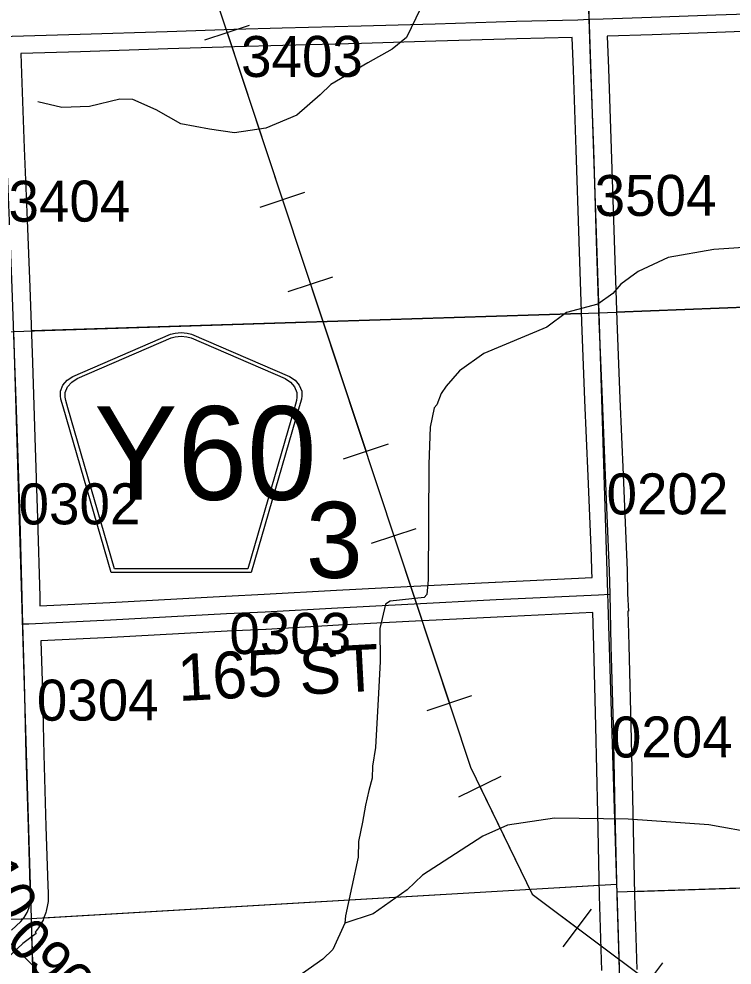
# Model space of a CAD drawing. Extents: x 128.7 to 185.5, y -21.4 to 12.6.
# Drawn here: x 149.009 to 150.229, y -2.33 to -0.713 of the extents above; entities that cross this region are included whole.
import ezdxf

# ---------------------------------------------------------------- set-up
doc = ezdxf.new("R2010")
doc.units = 0
for name, color, linetype in [('tdCoHydroRiver', 7, 'Continuous'), ('tdCoPipe', 7, 'Continuous'), ('tdCoPriDiv', 7, 'Continuous'), ('tdCoSecRdNmbr', 7, 'Continuous'), ('tdCoSecRdTxt', 7, 'Continuous'), ('tdCoSecRteBand', 7, 'Continuous'), ('tdCoSecRteCL', 7, 'Continuous'), ('tdCoSectLine', 7, 'Continuous'), ('tdCoSectLinePart', 7, 'Continuous'), ('tdCoSectNmbr', 7, 'Continuous'), ('tdCoShieldCoRteHrd', 7, 'Continuous'), ('tdCoSurfAsphalt', 7, 'Continuous'), ('tdCoSurfGravel', 7, 'Continuous'), ('tdCoTwpBndry', 7, 'Continuous'), ('tdCoTwpBndryShd', 7, 'Continuous')]:
    doc.layers.add(name, color=color, linetype=linetype)

msp = doc.modelspace()

# ---------------------------------------------------------------- linework, layer by layer
at = {"layer": 'tdCoHydroRiver'}
for points in [[(149.6958, -0.6948), (149.6722, -0.7446), (149.6477, -0.7644), (149.6059, -0.7879), (149.5424, -0.8248), (149.5241, -0.8428), (149.4842, -0.8773), (149.4314, -0.8996), (149.378, -0.9078), (149.3351, -0.9013), (149.2859, -0.892), (149.2441, -0.8682), (149.204, -0.8506), (149.1819, -0.8498), (149.1302, -0.8626), (149.0829, -0.8642), (149.0416, -0.8546)], [(150.3503, -1.0969), (150.1976, -1.1069), (150.1191, -1.1206), (150.0679, -1.1445), (150.0386, -1.166), (150.025, -1.1822), (149.9988, -1.2005), (149.9456, -1.2149), (149.9117, -1.2398), (149.8044, -1.2845), (149.7628, -1.3143), (149.74, -1.3404), (149.731, -1.3533), (149.7238, -1.3725), (149.7192, -1.3774), (149.7125, -1.4108), (149.7099, -1.474), (149.7088, -1.6713), (149.7065, -1.6966), (149.7019, -1.7015), (149.6438, -1.7082), (149.636, -1.7132), (149.6264, -1.7546), (149.6268, -1.8114), (149.6239, -1.8652), (149.6192, -1.9584), (149.614, -1.9902), (149.6131, -2.0107), (149.6075, -2.0314), (149.6021, -2.0569), (149.5967, -2.0855), (149.59, -2.1188), (149.5893, -2.1457), (149.5675, -2.2458), (149.5664, -2.2585), (149.5458, -2.3034), (149.529, -2.3198), (149.4397, -2.3828)], [(150.2713, -2.1049), (150.1887, -2.0904), (150.0511, -2.0809), (149.9248, -2.0789), (149.8447, -2.0911), (149.8027, -2.1099), (149.6993, -2.1766), (149.6733, -2.2012), (149.6148, -2.2427), (149.5664, -2.2585)]]:
    msp.add_lwpolyline(points, dxfattribs=at)
at = {"layer": 'tdCoPipe'}
for p, q in [((149.3271, -0.7486), (149.4035, -0.7233)), ((149.4218, -1.0344), (149.4983, -1.0091)), ((149.4697, -1.1788), (149.5461, -1.1535)), ((149.5644, -1.4647), (149.6409, -1.4393)), ((149.6122, -1.609), (149.6886, -1.5837)), ((149.707, -1.8949), (149.7835, -1.8695)), ((149.7613, -2.0424), (149.8337, -2.0072)), ((149.94, -2.2989), (149.9885, -2.2345)), ((150.0616, -2.3903), (150.11, -2.326))]:
    msp.add_line(p, q, dxfattribs=at)
for points in [[(148.6284, 1.2813), (148.7667, 0.7397), (148.8239, 0.5169), (149.0454, 0.2655), (149.1111, 0.0311), (149.7815, -1.9917), (149.8869, -2.2086), (150.0884, -2.36), (150.353, -3.1907), (150.6682, -4.2821), (150.7734, -4.4455), (150.8791, -4.6209), (150.9399, -4.7309), (150.9845, -4.7883), (151.1763, -4.8453), (151.8715, -6.5252), (151.9475, -6.6623), (151.9951, -7.1544), (151.9928, -7.2474), (152.3334, -7.551)], [(149.3653, -0.7359), (149.4601, -1.0218)], [(149.5079, -1.1661), (149.6027, -1.452)], [(149.6505, -1.5963), (149.7452, -1.8822)], [(149.7976, -2.0247), (149.8869, -2.2086), (149.9642, -2.2667)]]:
    msp.add_lwpolyline(points, dxfattribs=at)
at = {"layer": 'tdCoPriDiv'}
msp.add_lwpolyline([(148.9817, -2.2801), (149.0338, -2.3311)], dxfattribs=at)
at = {"layer": 'tdCoSecRteBand'}
for points in [[(150.3087, -0.7323), (150.2017, -0.736), (150.0922, -0.7399), (150.0921, -0.74), (150.092, -0.74), (150.0152, -0.7422), (150.0152, -0.7424), (150.0172, -0.7977), (150.0221, -0.9346), (150.0221, -0.9347), (150.0221, -0.9347), (150.0268, -1.091), (150.0315, -1.2282), (150.0369, -1.362), (150.0424, -1.492), (150.0424, -1.492), (150.0424, -1.492), (150.048, -1.6284), (150.048, -1.6284), (150.048, -1.6285), (150.049, -1.6551), (150.049, -1.6553), (150.049, -1.6555), (150.05, -1.6953), (150.0513, -1.7249), (150.0506, -1.7249), (150.052, -1.7835), (150.0557, -1.9205), (150.0557, -1.9206), (150.0557, -1.9207), (150.0589, -2.0691), (150.0589, -2.0692), (150.0589, -2.0692), (150.0619, -2.2098), (150.066, -2.3376)], [(149.0453, -1.7158), (149.1646, -1.7101), (149.3625, -1.6993), (149.3627, -1.6993), (149.3628, -1.6992), (149.4287, -1.6963), (149.5521, -1.6894), (149.5522, -1.6894), (149.5522, -1.6894), (149.6728, -1.683), (149.6728, -1.683), (149.6729, -1.683), (149.8238, -1.6753), (149.8238, -1.6753), (149.8239, -1.6753), (149.9893, -1.6676), (149.9893, -1.667), (149.9891, -1.6571), (149.9881, -1.6308), (149.9824, -1.4945), (149.977, -1.3645), (149.977, -1.3645), (149.977, -1.3645), (149.9716, -1.2306), (149.9716, -1.2305), (149.9715, -1.2304), (149.9669, -1.093), (149.9669, -1.093), (149.9669, -1.0929), (149.9622, -0.9366), (149.9572, -0.7999), (149.9572, -0.7999), (149.9572, -0.7999), (149.9553, -0.7446), (149.8606, -0.7466), (149.7219, -0.751), (149.7219, -0.7511), (149.7219, -0.7511), (149.5951, -0.7548), (149.5951, -0.7548), (149.595, -0.7548), (149.4604, -0.7582), (149.3779, -0.7604), (149.2638, -0.7641), (149.2638, -0.7641), (149.2637, -0.7641), (149.1148, -0.7688), (149.0124, -0.7721), (149.0135, -0.8063), (149.0182, -0.9339), (149.0232, -1.0567), (149.0278, -1.1711), (149.0278, -1.1712), (149.0278, -1.1713), (149.0323, -1.3002), (149.0367, -1.428), (149.0367, -1.428), (149.0367, -1.4281), (149.0412, -1.5667), (149.0412, -1.5667), (149.0412, -1.5668), (149.0449, -1.7002), (149.0453, -1.7158)], [(150.0061, -2.3395), (150.0019, -2.2116), (150.0019, -2.2114), (150.0019, -2.2112), (149.9989, -2.0704), (149.9957, -1.9221), (149.992, -1.785), (149.992, -1.785), (149.992, -1.7849), (149.9907, -1.7276), (149.8268, -1.7353), (149.6759, -1.7429), (149.5554, -1.7493), (149.4319, -1.7562), (149.4317, -1.7562), (149.4316, -1.7562), (149.3656, -1.7592), (149.1678, -1.77), (149.1677, -1.77), (149.1675, -1.77), (149.047, -1.7758), (149.047, -1.7759), (149.0488, -1.8447), (149.0488, -1.8448), (149.0488, -1.8448), (149.0518, -1.97), (149.0555, -2.0932), (149.0587, -2.1943), (149.0592, -2.2073), (149.0592, -2.2081), (149.0592, -2.209), (149.059, -2.2211), (149.0589, -2.2241), (149.0583, -2.227), (149.0558, -2.2381), (149.0554, -2.2401), (149.0546, -2.242), (149.0514, -2.2507), (149.0506, -2.253), (149.0494, -2.2551), (149.0444, -2.2637), (149.0429, -2.2664), (149.0408, -2.2688), (149.0385, -2.2713), (149.039, -2.2718), (149.0369, -2.2737), (149.0386, -2.2759), (149.016, -2.2933), (148.9875, -2.32)]]:
    msp.add_lwpolyline(points, dxfattribs=at)
at = {"layer": 'tdCoSecRteCL'}
for points in [[(149.9842, -0.7135), (149.9823, -0.6609), (149.9771, -0.5107), (149.9729, -0.3756), (149.969, -0.2444), (149.9638, -0.1021), (149.9586, 0.0269), (149.9557, 0.1368), (149.9502, 0.27), (149.9496, 0.2864)], [(149.9842, -0.7135), (150.0083, -0.7124), (150.0911, -0.71), (150.2006, -0.706), (150.3077, -0.7023), (150.4152, -0.6976), (150.4948, -0.6952), (150.6154, -0.6907), (150.7269, -0.6873), (150.8482, -0.6821), (150.9793, -0.6784)], [(148.9814, -0.7429), (148.9977, -0.7425), (149.1138, -0.7388), (149.2628, -0.7341), (149.377, -0.7304), (149.4596, -0.7282), (149.5942, -0.7248), (149.721, -0.7211), (149.8598, -0.7166), (149.9649, -0.7144), (149.9842, -0.7135)], [(150.02, -1.6963), (150.019, -1.6562), (150.0181, -1.6296), (150.0124, -1.4932), (150.007, -1.3633), (150.0015, -1.2294), (149.9968, -1.092), (149.9922, -0.9356), (149.9872, -0.7988), (149.9842, -0.7135)], [(149.0162, -1.7467), (149.0156, -1.7252), (149.0149, -1.701), (149.0112, -1.5676), (149.0067, -1.429), (149.0023, -1.3013), (148.9979, -1.1723), (148.9932, -1.0579), (148.9882, -0.9351), (148.9836, -0.8073), (148.9814, -0.7429)], [(149.0162, -1.7467), (149.026, -1.7467), (149.1661, -1.7401), (149.3641, -1.7292), (149.4302, -1.7263), (149.5538, -1.7194), (149.6744, -1.7129), (149.8253, -1.7053), (150.0004, -1.6972), (150.02, -1.6963)], [(150.0484, -2.7044), (150.0464, -2.6621), (150.0449, -2.602), (150.04, -2.4698), (150.0361, -2.3386), (150.0319, -2.2106), (150.0289, -2.0698), (150.0257, -1.9213), (150.022, -1.7842), (150.02, -1.6963)], [(148.9965, -2.2704), (149.0125, -2.2555), (149.0184, -2.2488), (149.0233, -2.2402), (149.0265, -2.2316), (149.029, -2.2205), (149.0292, -2.2084), (149.0287, -2.1953), (149.0255, -2.0941), (149.0218, -1.9708), (149.0188, -1.8455), (149.0162, -1.7467)]]:
    msp.add_lwpolyline(points, dxfattribs=at)
at = {"layer": 'tdCoSectLine'}
for points in [[(149.9674, -0.2114), (150.0007, -1.2153)], [(150.0007, -1.2153), (150.9999, -1.1762)], [(149.0001, -1.2471), (150.0007, -1.2153)], [(150.0007, -1.2153), (150.031, -2.1919)], [(149.0001, -1.2471), (149.03, -2.2503)], [(150.0314, -2.205), (151.0297, -2.1726)], [(149.03, -2.2503), (150.031, -2.1919)], [(150.031, -2.1919), (150.0314, -2.205)], [(150.0314, -2.205), (150.0624, -3.2061)], [(148.0268, -2.2837), (149.03, -2.2503)], [(149.03, -2.2503), (149.0603, -3.244)]]:
    msp.add_lwpolyline(points, dxfattribs=at)
at = {"layer": 'tdCoSectLinePart'}
for points in [[(150.0306, -1.2141), (150.9697, -1.1774)], [(149.0299, -1.2462), (149.9707, -1.2162)], [(150.0613, -2.204), (150.9999, -2.1736)], [(149.0516, -2.2491), (150.0011, -2.1937)], [(149.0308, -2.279), (149.0603, -3.244)]]:
    msp.add_lwpolyline(points, dxfattribs=at)
at = {"layer": 'tdCoShieldCoRteHrd'}
for points in [[(149.1669, -1.659), (149.0849, -1.3761), (149.081, -1.363), (149.0803, -1.3571), (149.0803, -1.3493), (149.0846, -1.3389), (149.0918, -1.3305), (149.1014, -1.3238), (149.2687, -1.2514), (149.2762, -1.2498), (149.2866, -1.2489), (149.2971, -1.2498), (149.3046, -1.2514), (149.4718, -1.3238), (149.4814, -1.3305), (149.4887, -1.3389), (149.4929, -1.3493), (149.4929, -1.3571), (149.4922, -1.363), (149.4883, -1.3761), (149.4064, -1.659)], [(149.1727, -1.6527), (149.093, -1.3774), (149.0893, -1.3648), (149.0886, -1.3591), (149.0886, -1.3516), (149.0926, -1.3417), (149.0996, -1.3336), (149.1088, -1.3272), (149.2694, -1.2577), (149.2766, -1.2561), (149.2866, -1.2553), (149.2966, -1.2561), (149.3039, -1.2577), (149.4644, -1.3272), (149.4736, -1.3336), (149.4806, -1.3417), (149.4847, -1.3516), (149.4847, -1.3591), (149.484, -1.3648), (149.4803, -1.3774), (149.4005, -1.6527)]]:
    msp.add_lwpolyline(points, close=True, dxfattribs=at)
at = {"layer": 'tdCoSurfAsphalt'}
msp.add_lwpolyline([(148.9965, -2.2704), (149.0125, -2.2555), (149.0184, -2.2488), (149.0233, -2.2402), (149.0265, -2.2316), (149.029, -2.2205), (149.0292, -2.2084), (149.0287, -2.1953), (149.0255, -2.0941), (149.0218, -1.9708), (149.0188, -1.8455), (149.0162, -1.7467), (149.0156, -1.7252), (149.0149, -1.701), (149.0112, -1.5676), (149.0067, -1.429)], dxfattribs=at)
at = {"layer": 'tdCoSurfGravel'}
for points in [[(149.9842, -0.7135), (149.9823, -0.6609), (149.9771, -0.5107), (149.9729, -0.3756), (149.969, -0.2444), (149.9638, -0.1021), (149.9586, 0.0269), (149.9557, 0.1368), (149.9502, 0.27), (149.9496, 0.2864)], [(148.9814, -0.7429), (148.9977, -0.7425), (149.1138, -0.7388), (149.2628, -0.7341), (149.377, -0.7304), (149.4596, -0.7282), (149.5942, -0.7248), (149.721, -0.7211), (149.8598, -0.7166), (149.9649, -0.7144), (149.9842, -0.7135), (150.0083, -0.7124), (150.0911, -0.71), (150.2006, -0.706), (150.3077, -0.7023), (150.4152, -0.6976), (150.4948, -0.6952), (150.6154, -0.6907), (150.7269, -0.6873), (150.8482, -0.6821), (150.9793, -0.6784)], [(150.0361, -2.3386), (150.0319, -2.2106), (150.0289, -2.0698), (150.0257, -1.9213), (150.022, -1.7842), (150.02, -1.6963), (150.019, -1.6562), (150.0181, -1.6296), (150.0124, -1.4932), (150.007, -1.3633), (150.0015, -1.2294), (149.9968, -1.092), (149.9922, -0.9356), (149.9872, -0.7988), (149.9842, -0.7135)], [(149.0162, -1.7467), (149.026, -1.7467), (149.1661, -1.7401), (149.3641, -1.7292), (149.4302, -1.7263), (149.5538, -1.7194), (149.6744, -1.7129), (149.8253, -1.7053), (150.0004, -1.6972), (150.02, -1.6963)]]:
    msp.add_lwpolyline(points, dxfattribs=at)
at = {"layer": 'tdCoTwpBndry'}
for points in [[(150.9699, -1.1774), (150.0307, -1.2141)], [(149.9707, -1.2162), (149.03, -1.2462)]]:
    msp.add_lwpolyline(points, dxfattribs=at)
at = {"layer": 'tdCoTwpBndryShd'}
msp.add_lwpolyline([(133.9673, -1.6731), (134.9785, -1.6501), (135.9787, -1.6285), (136.9783, -1.606), (136.9908, -1.6057), (137.9843, -1.5842), (138.9859, -1.5598), (139.9867, -1.5369), (141.001, -1.5077), (142.0055, -1.4764), (143.0036, -1.4478), (143.9967, -1.4154), (144.999, -1.3795), (146.001, -1.3445), (147.0006, -1.3151), (147.9961, -1.2801), (149.0001, -1.2471), (150.0007, -1.2153), (150.9999, -1.1762), (152.001, -1.1385), (152.9972, -1.0884), (154.0014, -1.05)], dxfattribs=at)

# ---------------------------------------------------------------- texts
at = {"layer": 'tdCoSecRdNmbr'}
for s, rotation, p in [('3403', 0.1135, (149.3892, -0.8121)), ('3504', 0.114, (149.9937, -1.0497)), ('3404', 0.1132, (148.9915, -1.0595)), ('0202', 0.114, (150.0141, -1.5598)), ('0302', 0.1132, (149.0087, -1.5769)), ('0303', 0.1135, (149.3692, -1.7984)), ('0304', 0.1132, (149.04, -1.9123)), ('0204', 0.114, (150.0215, -1.9753)), ('0410', 300.112, (148.8804, -2.0804)), ('0903', 315.1126, (148.9843, -2.2926))]:
    msp.add_text(s, height=0.07, rotation=rotation, dxfattribs=at).set_placement(p)
at = {"layer": 'tdCoSecRdTxt'}
msp.add_text('165 ST', height=0.08, rotation=3.0016, dxfattribs=at).set_placement((149.2824, -1.8789))
at = {"layer": 'tdCoSectNmbr'}
msp.add_text('3', height=0.13, rotation=0.1135, dxfattribs=at).set_placement((149.5002, -1.6684))
at = {"layer": 'tdCoShieldCoRteHrd'}
msp.add_text('Y60', height=0.16, dxfattribs=at).set_placement((149.1377, -1.5348))

doc.saveas('drawing.dxf')
